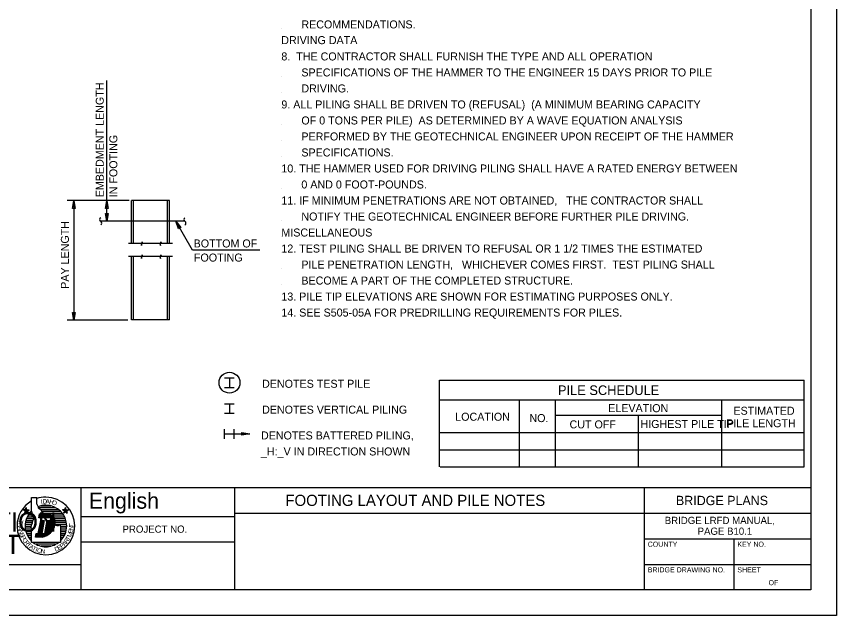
# Model space of a CAD drawing. Extents: x 0 to 181, y 0 to 126.
# Drawn here: x 95.9 to 181.3, y 0 to 62.4 of the extents above; entities that cross this region are included whole.
import ezdxf

# ---------------------------------------------------------------- set-up
doc = ezdxf.new("R2010")
doc.units = 0
for name, color, linetype in [('BORDER_ANNO_Cutsheet', 7, 'Continuous'), ('BRDG_ANNO_Anno-Sheet', 7, 'Continuous'), ('BRDG_ANNO_General-Notes', 7, 'Continuous'), ('BRDG_BASE_Active-Point', 7, 'Continuous'), ('BRDG_BASE_Obj-Line', 7, 'Continuous')]:
    doc.layers.add(name, color=color, linetype=linetype)

msp = doc.modelspace()

# ---------------------------------------------------------------- linework, layer by layer
at = {"layer": 'BORDER_ANNO_Cutsheet'}
msp.add_lwpolyline([(0, 117.333), (181.333, 117.333), (181.333, 0), (0, 0)], close=True, dxfattribs=at)
at = {"layer": 'BRDG_ANNO_Anno-Sheet'}
for p, q in [((8, 13.333), (102.667, 13.333)), ((102.667, 2.667), (102.667, 13.333)), ((102.667, 13.333), (178.667, 13.333)), ((118.667, 2.667), (118.667, 13.333)), ((161.333, 2.667), (161.333, 13.333)), ((97.517, 10.893), (97.517, 12.283)), ((97.517, 12.283), (98.043, 12.283)), ((98.043, 11.59), (98.043, 12.283)), ((96.883, 11.017), (96.957, 11.237)), ((96.957, 10.793), (96.957, 11.237)), ((97.03, 11.017), (96.957, 11.237)), ((98.043, 11.59), (98.183, 11.34)), ((98.183, 11.34), (98.21, 11.227)), ((98.21, 11.227), (98.487, 11.033)), ((98.223, 11.243), (100.003, 11.243)), ((98.48, 11.437), (99.51, 11.437)), ((100.97, 11.017), (101.043, 11.237)), ((101.043, 10.793), (101.043, 11.237)), ((101.117, 11.017), (101.043, 11.237)), ((97.073, 10.88), (96.653, 11.017)), ((96.883, 11.017), (96.653, 11.017)), ((96.84, 10.88), (96.653, 11.017)), ((97.03, 11.017), (96.767, 10.657)), ((96.84, 10.88), (96.767, 10.657)), ((96.957, 10.793), (96.767, 10.657)), ((96.84, 10.88), (97.263, 11.017)), ((96.883, 11.017), (97.147, 10.657)), ((96.957, 10.793), (97.147, 10.657)), ((97.03, 11.017), (97.263, 11.017)), ((97.05, 10.283), (97.59, 10.283)), ((97.073, 10.88), (97.263, 11.017)), ((97.073, 10.88), (97.147, 10.657)), ((97.157, 10.477), (97.56, 10.477)), ((97.29, 10.67), (97.567, 10.67)), ((97.463, 10.86), (97.527, 10.86)), ((97.57, 10.7), (97.517, 10.893)), ((97.57, 10.533), (97.57, 10.7)), ((97.57, 10.393), (97.57, 10.533)), ((97.6, 10.283), (97.57, 10.393)), ((97.71, 10.227), (97.6, 10.283)), ((98.267, 10.17), (98.35, 10.59)), ((98.343, 10.17), (98.42, 10.59)), ((98.35, 10.59), (99.267, 10.59)), ((98.427, 10.17), (98.507, 10.59)), ((98.48, 11.053), (100.303, 11.053)), ((98.487, 11.033), (98.573, 10.81)), ((98.513, 10.17), (98.59, 10.59)), ((98.553, 10.86), (100.537, 10.86)), ((98.573, 10.81), (98.85, 10.59)), ((98.597, 10.17), (98.677, 10.59)), ((98.68, 10.17), (98.76, 10.59)), ((98.75, 10.67), (100.707, 10.67)), ((98.767, 10.17), (98.843, 10.59)), ((98.85, 10.17), (98.93, 10.59)), ((98.937, 10.17), (99.013, 10.59)), ((99.02, 10.17), (99.1, 10.59)), ((99.107, 10.17), (99.183, 10.59)), ((99.19, 10.17), (99.27, 10.59)), ((99.197, 8.397), (99.583, 10.463)), ((99.273, 10.17), (99.35, 10.567)), ((99.293, 8.457), (99.66, 10.41)), ((99.36, 10.17), (99.43, 10.543)), ((99.393, 8.537), (99.73, 10.34)), ((99.443, 10.17), (99.507, 10.507)), ((99.497, 8.633), (99.8, 10.263)), ((99.567, 10.477), (100.84, 10.477)), ((99.787, 10.283), (100.947, 10.283)), ((101.16, 10.88), (100.737, 11.017)), ((100.927, 10.88), (100.737, 11.017)), ((100.97, 11.017), (100.737, 11.017)), ((101.117, 11.017), (100.853, 10.657)), ((100.927, 10.88), (100.853, 10.657)), ((101.043, 10.793), (100.853, 10.657)), ((100.927, 10.88), (101.347, 11.017)), ((100.97, 11.017), (101.233, 10.657)), ((101.043, 10.793), (101.233, 10.657)), ((101.117, 11.017), (101.347, 11.017)), ((101.16, 10.88), (101.347, 11.017)), ((101.16, 10.88), (101.233, 10.657)), ((102.667, 10.333), (118.667, 10.333)), ((118.667, 10.667), (161.333, 10.667)), ((161.333, 10.667), (178.667, 10.667)), ((96.84, 9.517), (97.55, 9.517)), ((96.867, 9.71), (97.59, 9.71)), ((96.91, 9.9), (97.66, 9.9)), ((96.967, 10.093), (97.7, 10.093)), ((97.487, 9.337), (97.517, 9.45)), ((97.517, 9.45), (97.6, 9.617)), ((97.6, 9.753), (97.653, 9.867)), ((97.6, 9.617), (97.6, 9.753)), ((97.653, 9.867), (97.71, 10.003)), ((97.71, 10.087), (97.71, 10.227)), ((97.71, 10.003), (97.71, 10.087)), ((98.21, 8.56), (98.46, 9.893)), ((98.22, 8.17), (98.543, 9.893)), ((99.527, 10.17), (98.267, 10.17)), ((98.307, 8.17), (98.63, 9.893)), ((98.39, 8.17), (98.713, 9.893)), ((98.46, 9.893), (98.827, 9.893)), ((98.477, 8.17), (98.8, 9.893)), ((98.827, 9.893), (98.577, 8.56)), ((98.9, 8.56), (99.15, 9.893)), ((98.917, 8.253), (99.223, 9.893)), ((99.007, 8.293), (99.307, 9.893)), ((99.1, 8.337), (99.393, 9.893)), ((99.15, 9.893), (99.477, 9.893)), ((99.477, 9.893), (99.527, 10.17)), ((99.603, 8.747), (99.867, 10.167)), ((99.717, 8.9), (99.93, 10.037)), ((99.85, 9.16), (99.977, 9.84)), ((99.907, 10.093), (101.03, 10.093)), ((99.95, 9.48), (99.99, 9.42)), ((99.96, 9.517), (101.16, 9.517)), ((99.97, 9.9), (101.09, 9.9)), ((99.987, 9.71), (101.133, 9.71)), ((99.99, 9.42), (100.157, 9.393)), ((100.323, 9.367), (100.407, 9.477)), ((100.407, 9.477), (100.517, 9.31)), ((96.833, 9.323), (97.48, 9.323)), ((96.843, 9.133), (97.5, 9.133)), ((96.87, 8.94), (97.59, 8.94)), ((96.913, 8.75), (97.513, 8.75)), ((96.98, 8.557), (97.507, 8.557)), ((97.433, 9.2), (97.487, 9.337)), ((97.517, 9.117), (97.433, 9.2)), ((97.57, 9.033), (97.517, 9.117)), ((97.517, 8.81), (97.6, 8.893)), ((97.517, 7.613), (97.517, 8.81)), ((97.6, 8.977), (97.57, 9.033)), ((97.6, 8.893), (97.6, 8.977)), ((97.917, 8.17), (97.99, 8.56)), ((97.967, 8.17), (98.04, 8.56)), ((97.99, 8.56), (98.21, 8.56)), ((98.053, 8.17), (98.127, 8.56)), ((98.137, 8.17), (98.21, 8.56)), ((98.56, 8.17), (98.633, 8.56)), ((98.577, 8.56), (98.9, 8.56)), ((98.647, 8.173), (98.72, 8.56)), ((98.737, 8.197), (98.803, 8.56)), ((98.827, 8.223), (98.887, 8.56)), ((100.157, 9.393), (100.323, 9.367)), ((100.507, 9.323), (101.167, 9.323)), ((100.517, 9.31), (100.517, 7.613)), ((100.517, 8.94), (101.13, 8.94)), ((100.517, 8.75), (101.087, 8.75)), ((100.517, 8.557), (101.02, 8.557)), ((100.52, 9.133), (101.157, 9.133)), ((97.063, 8.363), (97.507, 8.363)), ((97.173, 8.173), (97.51, 8.173)), ((97.31, 7.98), (97.507, 7.98)), ((97.48, 7.79), (97.513, 7.79)), ((98.627, 8.17), (97.917, 8.17)), ((100.517, 8.363), (100.933, 8.363)), ((100.517, 8.173), (100.827, 8.173)), ((100.517, 7.98), (100.693, 7.98)), ((161.333, 8), (178.667, 8)), ((170.667, 2.667), (170.667, 8)), ((100.517, 7.613), (97.517, 7.613)), ((100.003, 7.42), (97.983, 7.42)), ((99.513, 7.23), (98.493, 7.23)), ((102.667, 7.667), (118.667, 7.667)), ((74.667, 5.333), (102.667, 5.333)), ((161.333, 5.333), (178.667, 5.333))]:
    msp.add_line(p, q, dxfattribs=at)
msp.add_lwpolyline([(8, 114.667), (178.667, 114.667), (178.667, 2.667), (8, 2.667)], close=True, dxfattribs=at)
for centre, radius, start, end in [((99, 9.333), 3, 90, 108.596), ((99, 9.333), 3, 0, 90), ((99, 9.333), 3, 119.63312, 180), ((99, 9.333), 2.167, 90, 112.14518), ((99, 9.333), 2.167, 0, 90), ((99, 9.333), 2.167, 133.19257, 180), ((99.111, 9.729), 0.875, 343.49805, 79.73615), ((98.32, 9.804), 1.662, 280.64795, 348.77185), ((99, 9.333), 3, 180, 270), ((99, 9.333), 2.167, 180.26444, 226.79463), ((99, 9.333), 3, 270, 0), ((99, 9.333), 2.167, 314.427, 0), ((99, 9.333), 2.167, 232.5658, 270), ((99, 9.333), 2.167, 270, 307.45359)]:
    msp.add_arc(centre, radius, start, end, dxfattribs=at)
at = {"layer": 'BRDG_ANNO_General-Notes'}
for p, q in [((105.351, 43.217), (105.351, 55.712)), ((107.659, 43.217), (101.206, 43.217)), ((101.76, 42.387), (101.898, 43.217)), ((101.898, 43.217), (101.898, 30.744)), ((101.898, 43.217), (102.037, 42.387)), ((105.212, 42.387), (105.351, 43.217)), ((107.659, 43.217), (105.278, 43.217)), ((105.351, 41.05), (105.351, 43.217)), ((105.351, 43.217), (105.489, 42.387)), ((102.037, 42.387), (101.76, 42.387)), ((105.489, 42.387), (105.212, 42.387)), ((105.212, 41.88), (105.489, 41.88)), ((105.351, 41.05), (105.212, 41.88)), ((105.489, 41.88), (105.351, 41.05)), ((114.254, 38.041), (112.518, 41.05)), ((112.813, 40.262), (112.518, 41.05)), ((112.518, 41.05), (113.053, 40.401)), ((113.053, 40.401), (112.813, 40.262)), ((121.274, 38.041), (114.254, 38.041)), ((101.76, 31.574), (102.037, 31.574)), ((101.898, 30.744), (101.76, 31.574)), ((102.037, 31.574), (101.898, 30.744)), ((107.532, 30.744), (101.206, 30.744)), ((117.611, 24.753), (118.611, 24.753)), ((118.111, 24.753), (118.111, 23.753)), ((117.611, 23.753), (118.611, 23.753)), ((117.611, 22.06), (118.611, 22.06)), ((118.111, 22.06), (118.111, 21.06)), ((117.611, 21.06), (118.611, 21.06)), ((117.611, 18.414), (117.611, 19.414)), ((117.611, 18.914), (118.611, 18.914)), ((118.611, 18.414), (118.611, 19.414)), ((118.611, 18.914), (120.236, 18.914)), ((119.406, 18.776), (119.406, 19.052)), ((119.406, 19.052), (120.236, 18.914)), ((120.236, 18.914), (119.406, 18.776))]:
    msp.add_line(p, q, dxfattribs=at)
msp.add_circle((118.119, 24.248), 1.085, dxfattribs=at)
at = {"layer": 'BRDG_BASE_Active-Point'}
for p, q in [((123.52, 61.134), (123.52, 61.134)), ((125.604, 61.134), (125.604, 61.134)), ((123.52, 59.468), (123.52, 59.468)), ((125.604, 59.468), (125.604, 59.468)), ((123.52, 57.801), (123.52, 57.801)), ((125.604, 57.801), (125.604, 57.801)), ((123.52, 56.134), (123.52, 56.134)), ((125.604, 56.134), (125.604, 56.134)), ((123.52, 54.468), (123.52, 54.468)), ((125.604, 54.468), (125.604, 54.468)), ((123.52, 52.801), (123.52, 52.801)), ((125.604, 52.801), (125.604, 52.801)), ((123.52, 51.134), (123.52, 51.134)), ((125.604, 51.134), (125.604, 51.134)), ((123.52, 49.468), (123.52, 49.468)), ((125.604, 49.468), (125.604, 49.468)), ((123.52, 47.801), (123.52, 47.801)), ((125.604, 47.801), (125.604, 47.801)), ((123.52, 46.134), (123.52, 46.134)), ((125.604, 46.134), (125.604, 46.134)), ((123.52, 44.468), (123.52, 44.468)), ((125.604, 44.468), (125.604, 44.468)), ((123.52, 42.801), (123.52, 42.801)), ((125.604, 42.801), (125.604, 42.801)), ((123.52, 41.134), (123.52, 41.134)), ((125.604, 41.134), (125.604, 41.134)), ((123.52, 39.468), (123.52, 39.468)), ((125.604, 39.468), (125.604, 39.468)), ((123.52, 37.801), (123.52, 37.801)), ((125.604, 37.801), (125.604, 37.801)), ((123.52, 36.134), (123.52, 36.134)), ((125.604, 36.134), (125.604, 36.134)), ((123.52, 34.468), (123.52, 34.468)), ((125.604, 34.468), (125.604, 34.468)), ((123.52, 32.801), (123.52, 32.801)), ((125.604, 32.801), (125.604, 32.801))]:
    msp.add_line(p, q, dxfattribs=at)
at = {"layer": 'BRDG_BASE_Obj-Line'}
for p, q in [((111.882, 43.217), (107.907, 43.217)), ((107.907, 38.741), (107.907, 43.217)), ((108.131, 38.741), (108.131, 43.229)), ((111.659, 38.741), (111.659, 43.237)), ((111.882, 38.741), (111.882, 43.217)), ((113.47, 41.05), (104.71, 41.05)), ((108.906, 38.744), (107.605, 38.744)), ((108.906, 38.744), (108.973, 38.538)), ((108.973, 38.538), (109.025, 38.928)), ((109.025, 38.928), (109.077, 38.744)), ((110.858, 38.744), (109.077, 38.744)), ((110.858, 38.744), (110.925, 38.538)), ((110.925, 38.538), (110.977, 38.928)), ((110.977, 38.928), (111.03, 38.744)), ((112.184, 38.744), (111.03, 38.744)), ((108.906, 37.373), (107.605, 37.373)), ((107.907, 30.79), (107.907, 37.37)), ((108.131, 30.79), (108.131, 37.37)), ((108.906, 37.373), (108.973, 37.167)), ((108.973, 37.167), (109.025, 37.557)), ((109.025, 37.557), (109.077, 37.373)), ((110.858, 37.373), (109.077, 37.373)), ((110.858, 37.373), (110.925, 37.167)), ((110.925, 37.167), (110.977, 37.557)), ((110.977, 37.557), (111.03, 37.373)), ((112.184, 37.373), (111.03, 37.373)), ((111.659, 30.79), (111.659, 37.37)), ((111.882, 30.79), (111.882, 37.37)), ((111.882, 30.79), (107.907, 30.79)), ((139.995, 24.521), (177.961, 24.521)), ((139.995, 15.473), (139.995, 24.521)), ((177.961, 15.473), (177.961, 24.521)), ((139.995, 22.465), (177.9, 22.465)), ((148.31, 15.473), (148.31, 22.465)), ((152.052, 15.473), (152.052, 22.465)), ((169.386, 15.473), (169.386, 22.465)), ((152.077, 20.873), (169.386, 20.873)), ((160.718, 15.473), (160.718, 20.873)), ((139.995, 19.073), (177.961, 19.073)), ((139.995, 17.273), (177.961, 17.273)), ((140.064, 15.473), (177.961, 15.473))]:
    msp.add_line(p, q, dxfattribs=at)
for centre, start, end in [((104.801, 41.238), 115.98923, 244.01077), ((104.618, 40.863), 295.98923, 64.01077), ((113.562, 41.238), 115.98923, 244.01077), ((113.379, 40.863), 295.98923, 64.01077)]:
    msp.add_arc(centre, 0.209, start, end, dxfattribs=at)

# ---------------------------------------------------------------- texts
at = {"layer": 'BRDG_ANNO_Anno-Sheet'}
for s, height, p in [('English', 1.6667, (103.47, 11.13)), ('FOOTING LAYOUT AND PILE NOTES', 1.16334, (123.94, 11.417)), ('BRIDGE PLANS', 0.97, (164.606, 11.5)), ('TRANSPORTATION', 2, (75.45, 8.75)), ('BRIDGE LRFD MANUAL,', 0.75, (163.437, 9.538)), ('PROJECT NO.', 0.75, (106.982, 8.627)), ('PAGE B10.1', 0.75, (166.862, 8.413)), ('DEPARTMENT', 2, (77.97, 6.417)), ('COUNTY', 0.53, (161.667, 7.167)), ('KEY NO.', 0.53, (171, 7.167)), ('BRIDGE DRAWING NO.', 0.53, (161.667, 4.5)), ('SHEET', 0.53, (171, 4.5)), ('OF', 0.53, (174.246, 3.167))]:
    msp.add_text(s, height=height, dxfattribs=at).set_placement(p)
for s, rotation, p in [('I', 11.95188, (98.517, 11.617)), ('D', 5.21184, (98.673, 11.65)), ('A', 357.8718, (98.97, 11.67)), ('H', 349.63177, (99.317, 11.647)), ('O', 342.19173, (99.597, 11.59)), ('R', 266.0275, (96.14, 9.64)), ('T', 259.42648, (96.203, 10.003)), ('T', 90.49256, (101.877, 9.223)), ('A', 273.76404, (96.123, 9.283)), ('N', 280.37584, (96.153, 8.913)), ('S', 287.92792, (96.23, 8.553)), ('M', 67.71394, (101.603, 8.11)), ('E', 75.61046, (101.757, 8.517)), ('N', 83.19321, (101.84, 8.87)), ('P', 295.49755, (96.35, 8.217)), ('O', 302.64464, (96.51, 7.893)), ('R', 309.90789, (96.713, 7.587)), ('A', 45, (100.937, 7.203)), ('R', 52.33438, (101.193, 7.473)), ('T', 59.03624, (101.407, 7.76)), ('T', 317.1211, (96.947, 7.313)), ('A', 324.63754, (97.217, 7.07)), ('T', 331.75026, (97.517, 6.863)), ('I', 337.0213, (97.863, 6.687)), ('O', 343.32869, (98.04, 6.617)), ('N', 351.65981, (98.447, 6.507)), ('D', 22.98872, (100.017, 6.643)), ('E', 30.54757, (100.35, 6.793)), ('P', 37.66562, (100.657, 6.983))]:
    msp.add_text(s, height=0.463, rotation=rotation, dxfattribs=at).set_placement(p)
at = {"layer": 'BRDG_ANNO_General-Notes'}
for s, height, p in [('RECOMMENDATIONS.', 0.83333, (125.604, 61.134)), ('DRIVING DATA', 0.83333, (123.509, 59.497)), ('8.  THE CONTRACTOR SHALL FURNISH THE TYPE AND ALL OPERATION', 0.83333, (123.52, 57.801)), ('SPECIFICATIONS OF THE HAMMER TO THE ENGINEER 15 DAYS PRIOR TO PILE', 0.83333, (125.604, 56.134)), ('DRIVING.', 0.8333, (125.604, 54.468)), ('9. ALL PILING SHALL BE DRIVEN TO (REFUSAL)  (A MINIMUM BEARING CAPACITY', 0.83333, (123.52, 52.801)), ('OF 0 TONS PER PILE)  AS DETERMINED BY A WAVE EQUATION ANALYSIS', 0.83333, (125.604, 51.134)), ('PERFORMED BY THE GEOTECHNICAL ENGINEER UPON RECEIPT OF THE HAMMER', 0.83333, (125.604, 49.468)), ('SPECIFICATIONS.', 0.83333, (125.604, 47.801)), ('10. THE HAMMER USED FOR DRIVING PILING SHALL HAVE A RATED ENERGY BETWEEN', 0.83333, (123.52, 46.134)), ('0 AND 0 FOOT-POUNDS.', 0.83333, (125.604, 44.468)), ('11. IF MINIMUM PENETRATIONS ARE NOT OBTAINED,   THE CONTRACTOR SHALL', 0.83333, (123.52, 42.801)), ('NOTIFY THE GEOTECHNICAL ENGINEER BEFORE FURTHER PILE DRIVING.', 0.83333, (125.604, 41.134)), ('MISCELLANEOUS', 0.83333, (123.52, 39.468)), ('BOTTOM OF', 0.8333, (114.387, 38.329)), ('12. TEST PILING SHALL BE DRIVEN TO REFUSAL OR 1 1/2 TIMES THE ESTIMATED', 0.83333, (123.52, 37.801)), ('FOOTING', 0.8333, (114.416, 36.859)), ('PILE PENETRATION LENGTH,   WHICHEVER COMES FIRST.  TEST PILING SHALL', 0.83333, (125.604, 36.134)), ('BECOME A PART OF THE COMPLETED STRUCTURE.', 0.83333, (125.604, 34.468)), ('13. PILE TIP ELEVATIONS ARE SHOWN FOR ESTIMATING PURPOSES ONLY.', 0.83333, (123.52, 32.801)), ('14. SEE S505-05A FOR PREDRILLING REQUIREMENTS FOR PILES.', 0.83333, (123.52, 31.134)), ('DENOTES TEST PILE', 0.83333, (121.512, 23.72)), ('PILE SCHEDULE', 1, (152.32, 22.965)), ('DENOTES VERTICAL PILING', 0.83333, (121.512, 21.027)), ('ELEVATION', 0.8333, (157.553, 21.18)), ('ESTIMATED', 0.8333, (170.591, 20.912)), ('LOCATION', 0.8333, (141.624, 20.287)), ('NO.', 0.8333, (149.351, 20.147)), ('CUT OFF', 0.8333, (153.528, 19.491)), ('HIGHEST PILE TIP', 0.83333, (160.915, 19.533)), ('PILE LENGTH', 0.83333, (169.83, 19.612)), ('DENOTES BATTERED PILING,', 0.83333, (121.398, 18.339)), ('_H:_V IN DIRECTION SHOWN', 0.83333, (121.398, 16.672))]:
    msp.add_text(s, height=height, dxfattribs=at).set_placement(p)
for s, height, p in [('EMBEDMENT LENGTH', 0.83333, (105.026, 43.553)), ('IN FOOTING', 0.8333, (106.442, 43.553)), ('PAY LENGTH', 0.8333, (101.398, 34.024))]:
    msp.add_text(s, height=height, rotation=90, dxfattribs=at).set_placement(p)

doc.saveas('drawing.dxf')
